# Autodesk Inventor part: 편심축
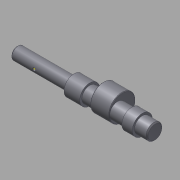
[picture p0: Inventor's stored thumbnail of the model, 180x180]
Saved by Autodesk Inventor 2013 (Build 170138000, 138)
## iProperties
Company: 한국ATC센터
Created: 2015-12
Part Number: 편심축
Document SubType Name: Modeling
Designer: mdu
Density: 7.86 g/cm^3
Mass: 218.607 g
Surface Area: 79.4502 cm^2
Volume: 27.8125 cm^3
Material: 강철, 연강
Author: mdu
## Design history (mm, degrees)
sketch "스케치1"
  geometry: L1 (-84.5, 0)-(84.5, 0); L2 (-84.5, 0)-(-84.5, 6); L3 (-84.5, 6)-(-30.5, 6); L4 (-30.5, 6)-(-30.5, 9.5); L5 (-30.5, 9.5)-(-15.5, 9.5); L6 (-15.5, 9.5)-(-15.5, 7.5); L7 (-15.5, 7.5)-(46.5, 7.5); L8 (84.5, 6)-(84.5, 0); L9 (34.5, 7.5)-(34.5, 9.5); L10 (34.5, 9.5)-(24.5, 9.5); L11 (24.5, 9.5)-(24.5, 7.5); L12 (46.5, 7.5)-(46.5, 6); L13 (46.5, 6)-(84.5, 6); 2 further points
  constraints: 26 end point, 6 parallel, 6 perpendicular, 2 point on line, 1 coincident, 1 horizontal, 1 midpoint
  dimensions: "d1" = 12 diameter of L3 L1; "d2" = 15 diameter of L7 L1; "d4" = 15 distance of L4.end L5.end; "d5" = 19 diameter of L5 L1; "d24" = 10 distance of L9.end L10.end; "d25" = 19 diameter of L10 L1; "d27" = 40 distance between parallel lines of L11 L6; "d28" = 54 distance of L2.end L3.end; "d29" = 50 distance between parallel lines of L8 L9; "d41" = 38 distance between parallel lines of L8 L12; "d42" = 12 diameter of L13 L1
revolve "회전1" stored, may be unused: angle "d6" = 90 deg
node "작업 평면1"
sketch "스케치2"
  geometry: C1 r 7.5 at (0, 0) reference; C2 r 12.5 at (0, 4.5); 1 further point
  constraints: 1 centre point, 1 vertical alignment
  dimensions: "d8" = 4.5 distance of point (0, 0) C2.centre; "d9" = 25 diameter of C2
extrude "돌출1" join sketch "스케치2" distance "d10" = 18; taper "d11" = 0 deg
chamfer "모따기1" distance "d12" = 1; stored, may be unused: second distance "d13" = 2, angle "d14" = 45 deg
chamfer "모따기2" distance "d15" = 0.5; stored, may be unused: second distance "d16" = 2, angle "d17" = 45 deg
node "작업 평면2"
sketch "스케치3"
  geometry: L1 (4, -2)-(18, -2); L2 (18, 2)-(4, 2); L3 (27, 5)-(27, -5) reference; A1 r 2 centre (18, 0) between (18, -2) and (18, 2); A2 r 2 centre (4, 0) between (4, 2) and (4, -2); 2 further points
  constraints: 4 end point, 4 point on circle, 4 tangent, 2 centre point, 1 horizontal, 1 horizontal alignment, 1 midpoint, 1 parallel
  dimensions: "d18" = 7 distance edge to line of A1 L3; "d19" = 4 distance between parallel lines of L2 L1; "d20" = 18 dimension on A1 A2
extrude "돌출2" cut sketch "스케치3" distance "d21" = 2.5; taper "d22" = 0 deg
revolve "회전2" stored, may be unused: angle "d26" = 90 deg
node "작업 평면3"
sketch "스케치4"
  geometry: L1 (44, 5)-(44, -5) reference; 2 further points
  constraints: 1 horizontal alignment
  dimensions: "d30" = 12 distance from line of point (32, 0) L1
hole "구멍1" sketch "스케치4" at (32, 0) diameter "d31" = 6; stored, may be unused: countersink angle "d35" = 90 deg, drill point angle "d37" = 118 deg; dims "d32" = 6, "d33" = 14, "d34" = 3, "d36" = 8
node "작업 평면4"
sketch "스케치5"
  geometry: C1 r 3 at (32, 0) reference; C2 r 8 at (32, 0); 2 further points
  constraints: 1 centre point, 1 coincident, 1 other
  dimensions: "d38" = 16 diameter of C2
extrude "돌출3" cut sketch "스케치5" distance "d39" = 3; taper "d40" = 0 deg
sketch "스케치6"
  geometry: L1 (-83.5, -6)-(-30.5, -6) reference; L2 (-84.5, -5)-(-84.5, 5) reference; L3 (-83.5, 6)-(-30.5, 6) reference; L4 (-62.5, 6)-(-62.5, -6); L5 (-62.5, -6)-(-61, -6); L6 (-62.5, -4.5)-(-61, -6); L7 (-62.5, -6)-(-62.5, -4.5); 2 further points
  constraints: 8 end point, 4 point on line, 2 perpendicular, 1 coincident
  dimensions: "d43" = 22 distance between parallel lines of L4 L2; "d44" = 45 deg angle of L6 L7; "d45" = 3 diameter of L5.end L4
revolve "회전3" stored, may be unused: angle "d46" = 90 deg
node "작업점1"
chamfer "모따기3" distance "d47" = 0.5; stored, may be unused: second distance "d48" = 2, angle "d49" = 45 deg
sketch "스케치7"
  geometry: C1 r 7.5 at (0, 0) reference; 1 further point
extrude "돌출4" cut sketch "스케치7" stored distance "d50" = 10; taper "d51" = 0 deg
chamfer "모따기4" distance "d52" = 1; stored, may be unused: second distance "d53" = 2, angle "d54" = 45 deg
node "작업 평면5"
node "솔리드1"
node "투영된 루프1"
other parameters: "d7" = 8.5
